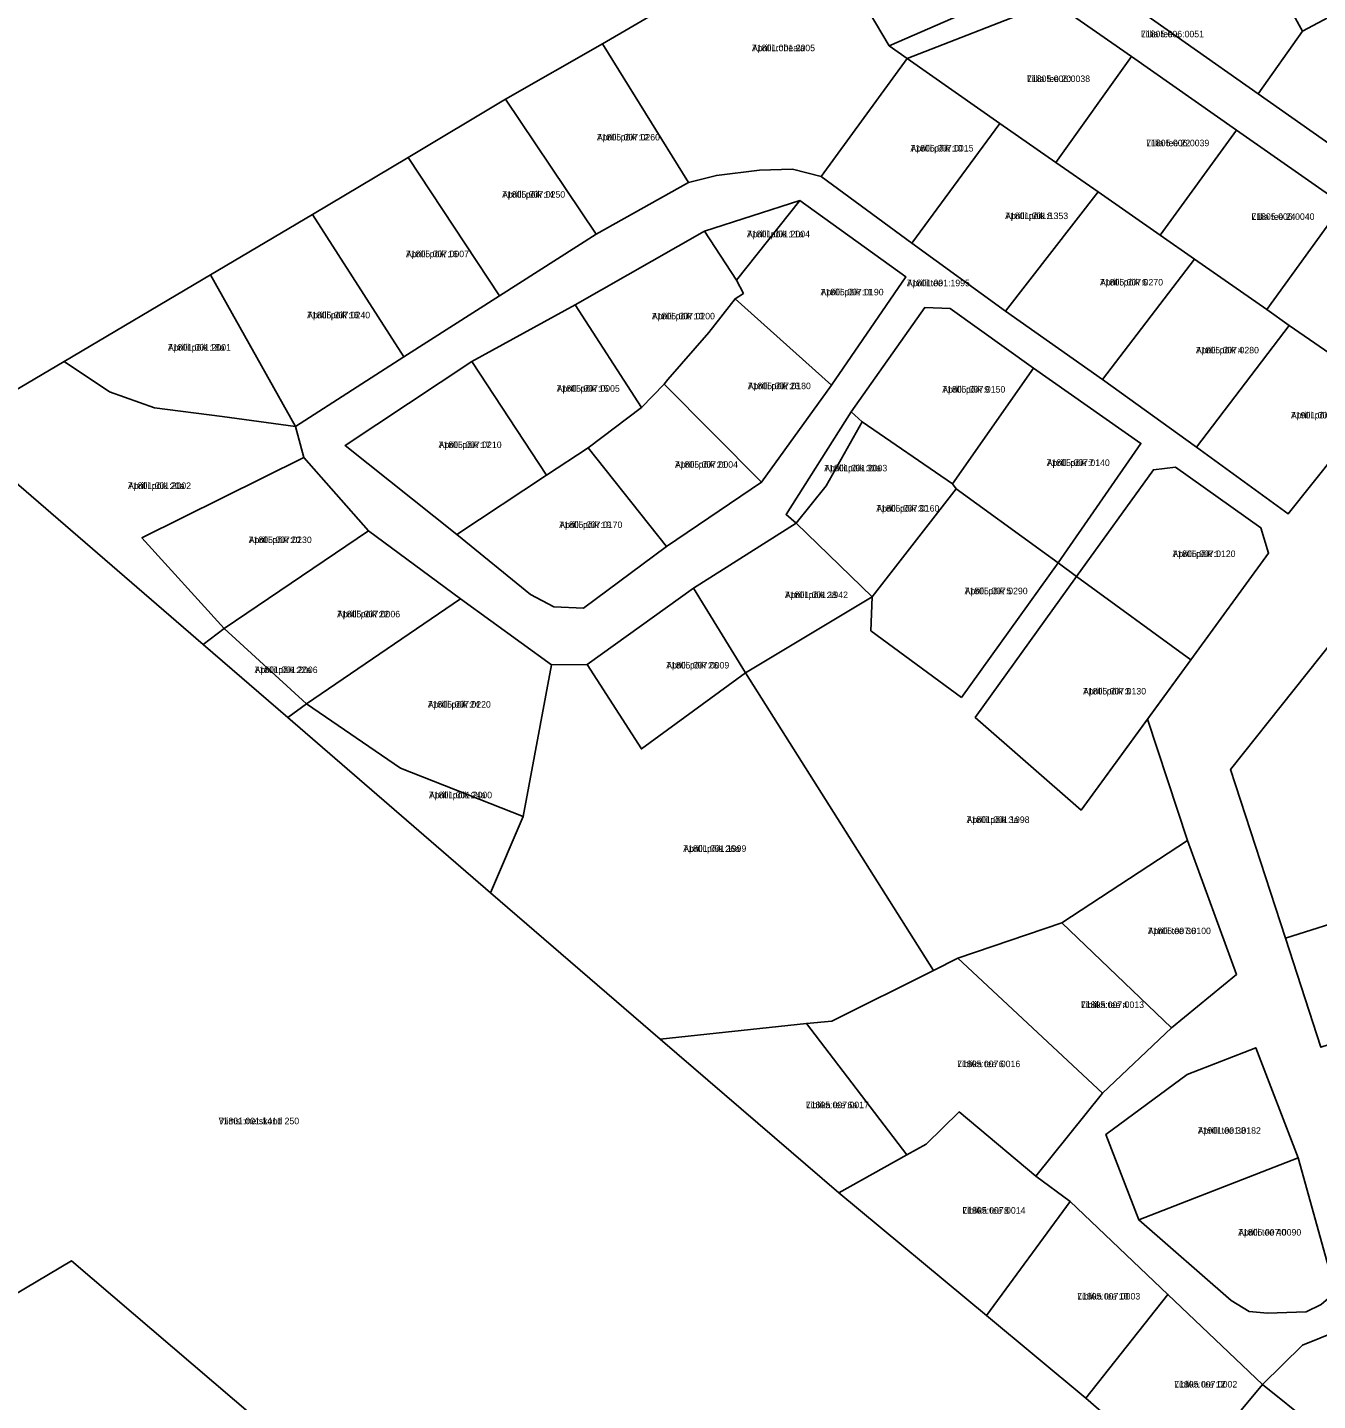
# Model space of a CAD drawing. Extents: x 529768 to 552006, y 6562269 to 6580975.
# Drawn here: x 537141.4 to 537438.1, y 6570909.2 to 6571224.9 of the extents above; entities that cross this region are included whole.
import ezdxf

# ---------------------------------------------------------------- set-up
doc = ezdxf.new("R2010")
doc.units = 0
for name, color, linetype in [('L_AADRESS', 7, 'Continuous'), ('PIIR', 7, 'Continuous'), ('TUNNUS', 7, 'Continuous')]:
    doc.layers.add(name, color=color, linetype=linetype)

msp = doc.modelspace()

# ---------------------------------------------------------------- linework, layer by layer
at = {"layer": 'PIIR'}
for points in [[(537500.31, 6571177.14), (537489.99, 6571171.59), (537474.12, 6571163.07), (537443.9, 6571184.21), (537419.45, 6571201.31), (537395.3, 6571218.2), (537377.23, 6571230.84), (537343.75, 6571217.76), (537339.6, 6571220.7), (537371.86, 6571234.8), (537396.97, 6571249.71), (537421.84, 6571264.48), (537442.4, 6571276.69), (537445.42, 6571282.22), (537449.08, 6571280.61), (537448.36, 6571271.95), (537460.05, 6571250.62), (537472.66, 6571227.61), (537485.53, 6571204.11)], [(537371.86, 6571234.8), (537339.6, 6571220.7), (537324.81, 6571245.7), (537354.9, 6571263.63)], [(537390.85, 6571233.33), (537424.42, 6571209.69), (537460.83, 6571184.07), (537479.5, 6571193.94), (537456.44, 6571235.68), (537440.86, 6571263.86), (537419.53, 6571251.4), (537390.92, 6571234.67)], [(537440.86, 6571263.86), (537456.44, 6571235.68), (537434.62, 6571224.09), (537419.53, 6571251.4)], [(537343.75, 6571217.76), (537323.94, 6571190.62), (537317.35, 6571192.32), (537309.75, 6571192.08), (537299.88, 6571190.9), (537293.42, 6571189.29), (537273.68, 6571221.14), (537322.52, 6571249.63), (537323.81, 6571247.48), (537324.81, 6571245.7), (537339.6, 6571220.7)], [(537390.85, 6571233.33), (537390.92, 6571234.67), (537419.53, 6571251.4), (537434.62, 6571224.09), (537424.42, 6571209.69)], [(537479.5, 6571193.94), (537460.83, 6571184.07), (537424.42, 6571209.69), (537434.62, 6571224.09), (537456.44, 6571235.68)], [(537377.23, 6571230.84), (537395.3, 6571218.2), (537377.95, 6571193.89), (537365.05, 6571202.83), (537343.75, 6571217.76)], [(537273.68, 6571221.14), (537293.42, 6571189.29), (537272.19, 6571177.35), (537251.33, 6571208.43)], [(537343.75, 6571217.76), (537365.05, 6571202.83), (537344.83, 6571175.29), (537323.94, 6571190.62)], [(537419.45, 6571201.31), (537401.9, 6571177.15), (537387.68, 6571187.09), (537377.95, 6571193.89), (537395.3, 6571218.2)], [(537251.33, 6571208.43), (537272.19, 6571177.35), (537249.97, 6571163.18), (537228.97, 6571194.99)], [(537344.83, 6571175.29), (537365.05, 6571202.83), (537377.95, 6571193.89), (537387.68, 6571187.09), (537366.35, 6571159.64)], [(537443.9, 6571184.21), (537426.41, 6571160.03), (537409.79, 6571171.64), (537401.9, 6571177.15), (537419.45, 6571201.31)], [(537206.95, 6571181.9), (537228.97, 6571194.99), (537249.97, 6571163.18), (537227.95, 6571149.17)], [(537387.68, 6571187.09), (537401.9, 6571177.15), (537409.79, 6571171.64), (537388.66, 6571143.93), (537366.35, 6571159.64)], [(537243.6, 6571148.09), (537214.46, 6571128.82), (537240.16, 6571108.31), (537257.12, 6571094.5), (537262.5, 6571091.7), (537269.28, 6571091.36), (537288.36, 6571105.6), (537310.25, 6571120.32), (537326.31, 6571142.68), (537343.41, 6571167.6), (537319.08, 6571185.1), (537297.1, 6571178.06), (537267.4, 6571161.15)], [(537297.1, 6571178.06), (537319.08, 6571185.1), (537304.46, 6571166.84)], [(537306.06, 6571163.76), (537304.46, 6571166.84), (537319.08, 6571185.1), (537343.41, 6571167.6), (537326.31, 6571142.68), (537304.21, 6571162.54)], [(537443.9, 6571184.21), (537474.12, 6571163.07), (537467.76, 6571159.65), (537453.72, 6571141.12), (537431.58, 6571156.41), (537426.41, 6571160.03)], [(537183.52, 6571168.06), (537206.95, 6571181.9), (537227.95, 6571149.17), (537203.04, 6571133.15)], [(537297.1, 6571178.06), (537304.46, 6571166.84), (537306.06, 6571163.76), (537304.21, 6571162.54), (537298.11, 6571154.81), (537288.7, 6571143.95), (537287.84, 6571142.92), (537282.67, 6571137.52), (537267.4, 6571161.15)], [(537409.79, 6571171.64), (537426.41, 6571160.03), (537431.58, 6571156.41), (537410.24, 6571128.44), (537388.66, 6571143.93)], [(537149.89, 6571148.07), (537183.52, 6571168.06), (537203.04, 6571133.15), (537186.24, 6571135.45), (537170.64, 6571137.45), (537160.28, 6571141.16)], [(537260.81, 6571121.97), (537243.6, 6571148.09), (537267.4, 6571161.15), (537282.67, 6571137.52), (537270.4, 6571128.26)], [(537288.7, 6571143.95), (537298.11, 6571154.81), (537304.21, 6571162.54), (537326.31, 6571142.68), (537310.25, 6571120.32), (537287.84, 6571142.92)], [(537330.86, 6571136.55), (537347.77, 6571160.5), (537353.65, 6571160.28), (537372.75, 6571146.6), (537354.15, 6571119.94), (537333.4, 6571134.2)], [(537453.72, 6571141.12), (537431.35, 6571113.1), (537410.24, 6571128.44), (537431.58, 6571156.41)], [(537125.77, 6571131.43), (537124.11, 6571132.89), (537149.89, 6571148.07), (537160.28, 6571141.16), (537170.64, 6571137.45), (537186.24, 6571135.45), (537203.04, 6571133.15), (537204.99, 6571126.02), (537167.76, 6571107.55), (537186.7, 6571086.68), (537181.82, 6571083.05)], [(537240.16, 6571108.31), (537214.46, 6571128.82), (537243.6, 6571148.09), (537260.81, 6571121.97)], [(537397.5, 6571129.26), (537378.45, 6571101.8), (537374.84, 6571104.44), (537355.02, 6571118.8), (537354.15, 6571119.94), (537372.75, 6571146.6)], [(537282.67, 6571137.52), (537287.84, 6571142.92), (537310.25, 6571120.32), (537288.36, 6571105.6), (537270.4, 6571128.26)], [(537318.24, 6571110.92), (537315.9, 6571112.89), (537330.86, 6571136.55), (537333.4, 6571134.2), (537325.1, 6571119.52)], [(537325.1, 6571119.52), (537333.4, 6571134.2), (537354.15, 6571119.94), (537355.02, 6571118.8), (537335.7, 6571093.99), (537318.24, 6571110.92)], [(537105.97, 6570914.22), (536999.17, 6571053.52), (537125.77, 6571131.43), (537181.82, 6571083.05), (537201.28, 6571066.25), (537247.89, 6571025.95), (537286.95, 6570992.3), (537327.98, 6570956.93), (537361.94, 6570928.76), (537384.82, 6570909.76), (537406.88, 6570890.58), (537309.68, 6570814), (537277.74, 6570833.43), (537151.54, 6570941.28)], [(537219.88, 6571109.15), (537186.7, 6571086.68), (537167.76, 6571107.55), (537204.99, 6571126.02)], [(537269.28, 6571091.36), (537262.5, 6571091.7), (537257.12, 6571094.5), (537240.16, 6571108.31), (537260.81, 6571121.97), (537270.4, 6571128.26), (537288.36, 6571105.6)], [(537382.66, 6571098.66), (537400.37, 6571123.21), (537405.42, 6571123.8), (537425.04, 6571109.86), (537426.83, 6571104.04), (537408.94, 6571079.51)], [(537356.26, 6571070.84), (537335.4, 6571086.2), (537335.7, 6571093.99), (537355.02, 6571118.8), (537374.84, 6571104.44), (537378.45, 6571101.8)], [(537294.6, 6571096), (537318.24, 6571110.92), (537335.7, 6571093.99), (537306.55, 6571076.48)], [(537219.88, 6571109.15), (537240.98, 6571093.54), (537205.57, 6571069.4), (537186.7, 6571086.68)], [(537356.26, 6571070.84), (537378.45, 6571101.8), (537382.66, 6571098.66), (537359.4, 6571066.28), (537383.74, 6571044.94), (537399.01, 6571065.86), (537408.22, 6571037.97), (537379.31, 6571019.05), (537355.35, 6571010.88), (537349.8, 6571008.07), (537306.55, 6571076.48), (537335.7, 6571093.99), (537335.4, 6571086.2)], [(537408.94, 6571079.51), (537383.74, 6571044.94), (537359.4, 6571066.28), (537382.66, 6571098.66)], [(537294.6, 6571096), (537306.55, 6571076.48), (537282.62, 6571059.02), (537270.14, 6571078.4)], [(537261.96, 6571078.35), (537255.4, 6571043.48), (537227.2, 6571054.62), (537205.57, 6571069.4), (537240.98, 6571093.54)], [(537418.1, 6571054.26), (537447.4, 6571091.06), (537454.93, 6571065.27), (537465.64, 6571030.96), (537466.86, 6571026.92), (537463.68, 6571025.91), (537430.75, 6571015.51)], [(537201.28, 6571066.25), (537181.82, 6571083.05), (537186.7, 6571086.68), (537205.57, 6571069.4)], [(537282.62, 6571059.02), (537306.55, 6571076.48), (537349.8, 6571008.07), (537326.4, 6570996.4), (537320.55, 6570995.88), (537286.95, 6570992.3), (537247.89, 6571025.95), (537255.4, 6571043.48), (537261.96, 6571078.35), (537270.14, 6571078.4)], [(537247.89, 6571025.95), (537201.28, 6571066.25), (537205.57, 6571069.4), (537227.2, 6571054.62), (537255.4, 6571043.48)], [(537379.31, 6571019.05), (537408.22, 6571037.97), (537419.5, 6571007.18), (537404.5, 6570994.9)], [(537430.75, 6571015.51), (537463.68, 6571025.91), (537466.86, 6571026.92), (537474.44, 6571001.94), (537471.33, 6571000.77), (537438.88, 6570990.41)], [(537355.35, 6571010.88), (537379.31, 6571019.05), (537404.5, 6570994.9), (537388.68, 6570979.83)], [(537343.69, 6570965.64), (537320.55, 6570995.88), (537326.4, 6570996.4), (537349.8, 6571008.07), (537355.35, 6571010.88), (537388.68, 6570979.83), (537373.3, 6570960.8), (537355.71, 6570975.54), (537348.1, 6570968.1)], [(537286.95, 6570992.3), (537320.55, 6570995.88), (537343.69, 6570965.64), (537327.98, 6570956.93)], [(537433.61, 6570965.01), (537423.88, 6570990.29), (537408.09, 6570984.15), (537389.42, 6570970.36), (537396.98, 6570950.75), (537418.21, 6570932.21), (537422.36, 6570929.64), (537426.56, 6570929.24), (537435.5, 6570929.56), (537438.95, 6570931.25), (537442.2, 6570934.07)], [(537433.61, 6570965.01), (537396.98, 6570950.75), (537389.42, 6570970.36), (537408.09, 6570984.15), (537423.88, 6570990.29)], [(537355.71, 6570975.54), (537373.3, 6570960.8), (537381.18, 6570954.96), (537361.94, 6570928.76), (537327.98, 6570956.93), (537343.69, 6570965.64), (537348.1, 6570968.1)], [(537433.61, 6570965.01), (537442.2, 6570934.07), (537438.95, 6570931.25), (537435.5, 6570929.56), (537426.56, 6570929.24), (537422.36, 6570929.64), (537418.21, 6570932.21), (537396.98, 6570950.75)], [(537361.94, 6570928.76), (537381.18, 6570954.96), (537403.7, 6570933.6), (537384.82, 6570909.76)], [(537105.97, 6570914.22), (537151.54, 6570941.28), (537277.74, 6570833.43), (537205, 6570780.99)], [(537384.82, 6570909.76), (537403.7, 6570933.6), (537425.45, 6570912.88), (537406.88, 6570890.58)], [(537447.95, 6570894.76), (537425.45, 6570912.88), (537434.62, 6570921.92), (537446.57, 6570926.76), (537447.57, 6570924.58), (537455.75, 6570905.4)], [(537425.45, 6570912.88), (537447.95, 6570894.76), (537430.43, 6570870.99), (537406.88, 6570890.58)]]:
    msp.add_lwpolyline(points, close=True, dxfattribs=at)
for points in [[(537322.52, 6571249.63), (537273.68, 6571221.14), (537251.33, 6571208.43), (537228.97, 6571194.99), (537206.95, 6571181.9), (537183.52, 6571168.06), (537149.89, 6571148.07), (537124.11, 6571132.89), (537125.77, 6571131.43), (536999.17, 6571053.52), (536998.23, 6571054.73), (536921.7, 6571153.98), (536919.93, 6571156.36), (536939.3, 6571181.48), (536993.07, 6571243.33)], [(537446.57, 6570926.76), (537434.62, 6570921.92), (537425.45, 6570912.88), (537403.7, 6570933.6), (537381.18, 6570954.96), (537373.3, 6570960.8), (537388.68, 6570979.83), (537404.5, 6570994.9), (537419.5, 6571007.18), (537408.22, 6571037.97), (537399.01, 6571065.86), (537408.94, 6571079.51), (537426.83, 6571104.04), (537425.04, 6571109.86), (537405.42, 6571123.8), (537400.37, 6571123.21), (537382.66, 6571098.66), (537378.45, 6571101.8), (537397.5, 6571129.26), (537372.75, 6571146.6), (537353.65, 6571160.28), (537347.77, 6571160.5), (537330.86, 6571136.55), (537315.9, 6571112.89), (537318.24, 6571110.92), (537294.6, 6571096), (537270.14, 6571078.4), (537261.96, 6571078.35), (537240.98, 6571093.54), (537219.88, 6571109.15), (537204.99, 6571126.02), (537203.04, 6571133.15), (537227.95, 6571149.17), (537249.97, 6571163.18), (537272.19, 6571177.35), (537293.42, 6571189.29), (537299.88, 6571190.9), (537309.75, 6571192.08), (537317.35, 6571192.32), (537323.94, 6571190.62), (537344.83, 6571175.29), (537366.35, 6571159.64), (537388.66, 6571143.93), (537410.24, 6571128.44), (537431.35, 6571113.1), (537453.72, 6571141.12)], [(537447.4, 6571091.06), (537418.1, 6571054.26), (537430.75, 6571015.51), (537438.88, 6570990.41)]]:
    msp.add_lwpolyline(points, dxfattribs=at)

# ---------------------------------------------------------------- texts
at = {"layer": 'L_AADRESS'}
for s, p in [('Liilia tee', (537397.48, 6571222.65)), ('Aprilli roheala', (537308.04, 6571219.46)), ('Liilia tee 20', (537371.29, 6571212.37)), ('Aprilli põik 12', (537272.38, 6571198.93)), ('Liilia tee 22', (537398.7, 6571197.6)), ('Aprilli põik 10', (537344.49, 6571196.39)), ('Aprilli põik 14', (537250.58, 6571185.77)), ('Aprilli põik 8', (537366.25, 6571180.85)), ('Liilia tee 24', (537422.9, 6571180.67)), ('Aprilli põik 11a', (537306.88, 6571176.67)), ('Aprilli põik 16', (537228.46, 6571172.09)), ('Aprilli tee', (537343.65, 6571165.41)), ('Aprilli põik 6', (537388.07, 6571165.58)), ('Aprilli põik 11', (537323.81, 6571163.31)), ('Aprilli põik 18', (537205.74, 6571158.03)), ('Aprilli põik 13', (537285.02, 6571157.79)), ('Aprilli põik 18a', (537173.72, 6571150.6)), ('Aprilli põik 4', (537410.12, 6571149.97)), ('Aprilli põik 15', (537263.14, 6571141.15)), ('Aprilli põik 23', (537307.08, 6571141.74)), ('Aprilli põik 9', (537351.8, 6571140.95)), ('Aprilli põik 2', (537431.98, 6571135.01)), ('Aprilli põik 17', (537235.97, 6571128.2)), ('Aprilli põik 21', (537290.32, 6571123.67)), ('Aprilli põik 30a', (537324.65, 6571122.84)), ('Aprilli põik 7', (537375.82, 6571124.08)), ('Aprilli põik 20a', (537164.55, 6571118.79)), ('Aprilli põik 30', (537336.63, 6571113.58)), ('Aprilli põik 19', (537263.73, 6571109.81)), ('Aprilli põik 20', (537192.3, 6571106.35)), ('Aprilli põik 1', (537404.74, 6571103.14)), ('Aprilli põik 28', (537315.61, 6571093.7)), ('Aprilli põik 5', (537356.93, 6571094.59)), ('Aprilli põik 22', (537212.63, 6571089.27)), ('Aprilli põik 26', (537288.32, 6571077.51)), ('Aprilli põik 22a', (537193.65, 6571076.46)), ('Aprilli põik 3', (537384.17, 6571071.54)), ('Aprilli põik 24', (537233.49, 6571068.51)), ('Aprilli põik 24a', (537233.77, 6571047.67)), ('Aprilli põik 3a', (537357.38, 6571041.99)), ('Aprilli põik 26a', (537292.24, 6571035.35)), ('Aprilli tee 36', (537399.07, 6571016.43)), ('Liblika tee 4', (537383.7, 6570999.44)), ('Liblika tee 6', (537355.23, 6570985.84)), ('Liblika tee 6a', (537320.42, 6570976.4)), ('Viimsi metskond 250', (537185.4, 6570972.71)), ('Aprilli tee 38', (537410.56, 6570970.52)), ('Liblika tee 8', (537356.43, 6570952.15)), ('Aprilli tee 40', (537419.85, 6570947.12)), ('Liblika tee 10', (537382.82, 6570932.41)), ('Liblika tee 12', (537405.14, 6570912.17))]:
    msp.add_text(s, height=1.5, dxfattribs=at).set_placement(p)
at = {"layer": 'TUNNUS'}
for s, p in [('71805:006:0051', (537397.48, 6571222.65)), ('71801:001:2005', (537308.04, 6571219.46)), ('71805:006:0038', (537371.29, 6571212.37)), ('71805:007:0260', (537272.38, 6571198.93)), ('71805:006:0039', (537398.7, 6571197.6)), ('71805:007:0015', (537344.49, 6571196.39)), ('71805:007:0250', (537250.58, 6571185.77)), ('71801:001:1353', (537366.25, 6571180.85)), ('71805:006:0040', (537422.9, 6571180.67)), ('71801:001:2004', (537306.88, 6571176.67)), ('71805:007:0007', (537228.46, 6571172.09)), ('71805:007:0270', (537388.07, 6571165.58)), ('71805:007:0190', (537323.81, 6571163.31)), ('71801:001:1995', (537343.65, 6571165.41)), ('71805:007:0240', (537205.74, 6571158.03)), ('71805:007:0200', (537285.02, 6571157.79)), ('71801:001:2001', (537173.72, 6571150.6)), ('71805:007:0280', (537410.12, 6571149.97)), ('71805:007:0005', (537263.14, 6571141.15)), ('71805:007:0180', (537307.08, 6571141.74)), ('71805:007:0150', (537351.8, 6571140.95)), ('71901:001:0174', (537431.98, 6571135.01)), ('71805:007:0210', (537235.97, 6571128.2)), ('71805:007:0004', (537290.32, 6571123.67)), ('71801:001:2003', (537324.65, 6571122.84)), ('71805:007:0140', (537375.82, 6571124.08)), ('71801:001:2002', (537164.55, 6571118.79)), ('71805:007:0160', (537336.63, 6571113.58)), ('71805:007:0170', (537263.73, 6571109.81)), ('71805:007:0230', (537192.3, 6571106.35)), ('71805:007:0120', (537404.74, 6571103.14)), ('71801:001:1942', (537315.61, 6571093.7)), ('71805:007:0290', (537356.93, 6571094.59)), ('71805:007:0006', (537212.63, 6571089.27)), ('71805:007:0009', (537288.32, 6571077.51)), ('71801:001:2006', (537193.65, 6571076.46)), ('71805:007:0130', (537384.17, 6571071.54)), ('71805:007:0220', (537233.49, 6571068.51)), ('71801:001:2000', (537233.77, 6571047.67)), ('71801:001:1998', (537357.38, 6571041.99)), ('71801:001:1999', (537292.24, 6571035.35)), ('71805:007:0100', (537399.07, 6571016.43)), ('71805:007:0013', (537383.7, 6570999.44)), ('71805:007:0016', (537355.23, 6570985.84)), ('71805:007:0017', (537320.42, 6570976.4)), ('71801:001:1411', (537185.4, 6570972.71)), ('71901:001:0182', (537410.56, 6570970.52)), ('71805:007:0014', (537356.43, 6570952.15)), ('71805:007:0090', (537419.85, 6570947.12)), ('71805:007:0003', (537382.82, 6570932.41)), ('71805:007:0002', (537405.14, 6570912.17))]:
    msp.add_text(s, height=1.5, dxfattribs=at).set_placement(p)

doc.saveas('drawing.dxf')
